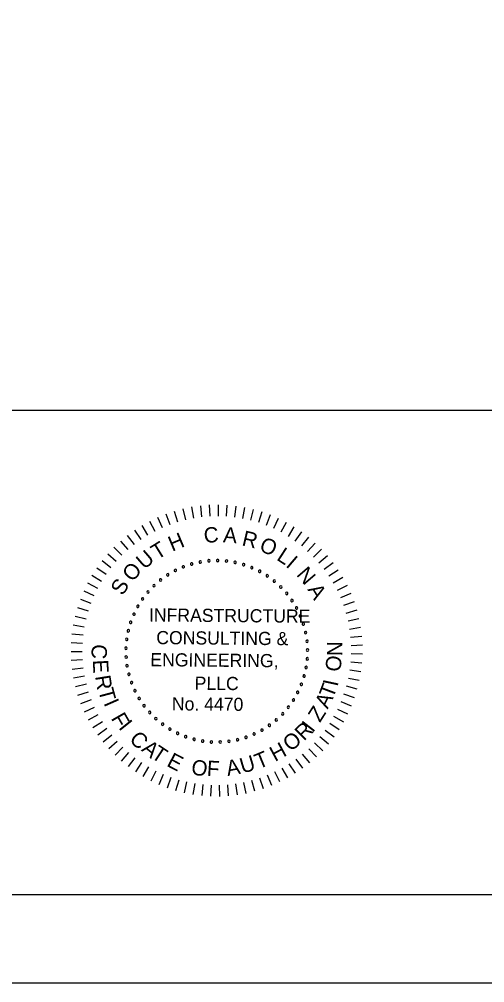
# Model space of a CAD drawing. Extents: x -133.1 to -97, y -1.8 to 20.5.
# Drawn here: x -107.93 to -105.29, y -1.69 to 3.78 of the extents above; entities that cross this region are included whole.
import ezdxf

# ---------------------------------------------------------------- set-up
doc = ezdxf.new("R2010")
doc.units = 0
for name, color, linetype in [('BR_BORDER LINES', 7, 'Continuous'), ('BR_TEXT', 7, 'Continuous'), ('Level 31', 7, 'Continuous')]:
    doc.layers.add(name, color=color, linetype=linetype)

msp = doc.modelspace()

# ---------------------------------------------------------------- linework, layer by layer
at = {"layer": 'BR_BORDER LINES'}
for p, q in [((-110.5071, 1.5591), (-105.1419, 1.5591)), ((-131.3076, -1.191), (-97.6416, -1.191))]:
    msp.add_line(p, q, dxfattribs=at)
at = {"layer": 'BR_TEXT'}
for p, q in [((-107.0494, 0.9866), (-107.0308, 0.9257)), ((-107.0007, 0.9998), (-106.9858, 0.9379)), ((-106.9512, 1.01), (-106.9401, 0.9473)), ((-106.9012, 1.0172), (-106.894, 0.9539)), ((-106.8509, 1.0213), (-106.8476, 0.9578)), ((-106.8005, 1.0224), (-106.801, 0.9587)), ((-106.75, 1.0204), (-106.7544, 0.9569)), ((-106.6998, 1.0153), (-106.7081, 0.9522)), ((-106.65, 1.0071), (-106.6621, 0.9446)), ((-106.6007, 0.996), (-106.6166, 0.9343)), ((-107.1439, 0.9513), (-107.1181, 0.8932)), ((-107.0972, 0.9704), (-107.0749, 0.9107)), ((-106.5523, 0.9818), (-106.5719, 0.9213)), ((-106.5048, 0.9648), (-106.528, 0.9055)), ((-106.4584, 0.9448), (-106.4852, 0.8871)), ((-107.276, 0.8776), (-107.24, 0.8251)), ((-107.2335, 0.9049), (-107.2008, 0.8503)), ((-107.1895, 0.9295), (-107.1601, 0.873)), ((-106.4133, 0.9221), (-106.4436, 0.8661)), ((-106.3697, 0.8967), (-106.4034, 0.8426)), ((-107.3168, 0.8478), (-107.2776, 0.7976)), ((-106.3277, 0.8686), (-106.3646, 0.8167)), ((-106.2875, 0.8381), (-106.3275, 0.7885)), ((-107.3925, 0.7811), (-107.3475, 0.736)), ((-107.3557, 0.8156), (-107.3135, 0.7679)), ((-106.2493, 0.8051), (-106.2922, 0.7581)), ((-106.2131, 0.7699), (-106.2588, 0.7256)), ((-107.4272, 0.7444), (-107.3795, 0.7022)), ((-106.1791, 0.7326), (-106.2275, 0.6911)), ((-107.4895, 0.665), (-107.437, 0.6289)), ((-107.4595, 0.7056), (-107.4094, 0.6664)), ((-106.1475, 0.6932), (-106.1983, 0.6548)), ((-107.5169, 0.6226), (-107.4623, 0.5897)), ((-106.1184, 0.652), (-106.1714, 0.6167)), ((-106.0918, 0.6091), (-106.1469, 0.5771)), ((-107.5416, 0.5786), (-107.4852, 0.5491)), ((-106.0679, 0.5646), (-106.1248, 0.5361)), ((-107.5637, 0.5332), (-107.5055, 0.5072)), ((-106.0467, 0.5188), (-106.1052, 0.4938)), ((-107.5992, 0.4387), (-107.5384, 0.42)), ((-107.5829, 0.4865), (-107.5233, 0.4641)), ((-106.0283, 0.4718), (-106.0883, 0.4504)), ((-107.6126, 0.3901), (-107.5507, 0.3751)), ((-106.0129, 0.4237), (-106.0741, 0.406)), ((-107.623, 0.3407), (-107.5604, 0.3295)), ((-106.0004, 0.3748), (-106.0625, 0.3608)), ((-107.6304, 0.2907), (-107.5672, 0.2834)), ((-105.9909, 0.3252), (-106.0538, 0.3151)), ((-105.9845, 0.2751), (-106.0479, 0.2689)), ((-107.6348, 0.2404), (-107.5712, 0.237)), ((-105.9811, 0.2247), (-106.0448, 0.2224)), ((-107.636, 0.19), (-107.5723, 0.1904)), ((-105.9809, 0.1743), (-106.0445, 0.1758)), ((-107.6342, 0.1395), (-107.5706, 0.1438)), ((-105.9836, 0.1239), (-106.0471, 0.1292)), ((-107.6293, 0.0893), (-107.5661, 0.0974)), ((-105.9895, 0.0737), (-106.0525, 0.0829)), ((-107.6213, 0.0394), (-107.5588, 0.0514)), ((-107.6103, -0.0099), (-107.5487, 0.0059)), ((-105.9984, 0.024), (-106.0607, 0.0371)), ((-107.5964, -0.0584), (-107.5358, -0.0388)), ((-106.0252, -0.0733), (-106.0855, -0.0527)), ((-106.0103, -0.025), (-106.0717, -0.0082)), ((-107.5795, -0.106), (-107.5202, -0.0828)), ((-106.043, -0.1205), (-106.1019, -0.0963)), ((-107.5597, -0.1524), (-107.5019, -0.1256)), ((-106.0636, -0.1666), (-106.1209, -0.1389)), ((-107.5371, -0.1976), (-107.4811, -0.1673)), ((-107.5119, -0.2413), (-107.4578, -0.2077)), ((-106.087, -0.2113), (-106.1426, -0.1802)), ((-107.484, -0.2834), (-107.4321, -0.2465)), ((-106.1418, -0.2961), (-106.1931, -0.2584)), ((-106.1131, -0.2545), (-106.1667, -0.22)), ((-107.4536, -0.3237), (-107.404, -0.2837)), ((-107.4208, -0.362), (-107.3737, -0.3191)), ((-106.173, -0.3358), (-106.2219, -0.2951)), ((-107.3857, -0.3983), (-107.3413, -0.3527)), ((-106.2423, -0.4092), (-106.2859, -0.3628)), ((-106.2065, -0.3735), (-106.2529, -0.3299)), ((-107.3485, -0.4324), (-107.307, -0.3841)), ((-107.3092, -0.4642), (-107.2708, -0.4135)), ((-106.32, -0.4736), (-106.3576, -0.4222)), ((-106.2801, -0.4426), (-106.3208, -0.3936)), ((-107.2681, -0.4935), (-107.2328, -0.4405)), ((-107.2253, -0.5203), (-107.1933, -0.4652)), ((-107.1809, -0.5444), (-107.1523, -0.4875)), ((-106.4049, -0.528), (-106.436, -0.4725)), ((-106.3616, -0.5021), (-106.3961, -0.4485)), ((-107.1352, -0.5657), (-107.1101, -0.5072)), ((-107.0882, -0.5842), (-107.0668, -0.5243)), ((-107.0402, -0.5998), (-107.0225, -0.5387)), ((-106.5915, -0.6041), (-106.6083, -0.5427)), ((-106.5432, -0.5894), (-106.5637, -0.5291)), ((-106.4959, -0.5718), (-106.52, -0.5128)), ((-106.4498, -0.5513), (-106.4774, -0.4939)), ((-106.9913, -0.6125), (-106.9773, -0.5504)), ((-106.9418, -0.6221), (-106.9316, -0.5593)), ((-106.8918, -0.6288), (-106.8854, -0.5654)), ((-106.8414, -0.6323), (-106.8389, -0.5687)), ((-106.7909, -0.6328), (-106.7923, -0.5691)), ((-106.7405, -0.6302), (-106.7458, -0.5667)), ((-106.6903, -0.6245), (-106.6995, -0.5615)), ((-106.6406, -0.6158), (-106.6536, -0.5535))]:
    msp.add_line(p, q, dxfattribs=at)
for centre, start, end in [((-106.8527, 0.7043), 5.0653, 185.0653), ((-106.8029, 0.7062), 359.5268, 179.5268), ((-107.0431, 0.6496), 27.2191, 207.2191), ((-106.9977, 0.6702), 21.6807, 201.6807), ((-106.9977, 0.6702), 201.6807, 21.6807), ((-106.9506, 0.6862), 16.1422, 196.1422), ((-106.9506, 0.6862), 196.1422, 16.1422), ((-106.9021, 0.6977), 10.6038, 190.6038), ((-106.9021, 0.6977), 190.6038, 10.6038), ((-106.8527, 0.7043), 185.0653, 5.0653), ((-106.8029, 0.7062), 179.5268, 359.5268), ((-106.7531, 0.7033), 173.9884, 353.9884), ((-106.7531, 0.7033), 353.9884, 173.9884), ((-106.7039, 0.6956), 168.4499, 348.4499), ((-106.7039, 0.6956), 348.4499, 168.4499), ((-106.6557, 0.6832), 162.9114, 342.9114), ((-106.6557, 0.6832), 342.9114, 162.9114), ((-106.6088, 0.6662), 157.373, 337.373), ((-106.6088, 0.6662), 337.373, 157.373), ((-107.127, 0.5959), 38.2961, 218.2961), ((-107.0864, 0.6248), 32.7576, 212.7576), ((-107.0864, 0.6248), 212.7576, 32.7576), ((-107.0431, 0.6496), 207.2191, 27.2191), ((-106.5639, 0.6447), 151.8345, 331.8345), ((-106.5639, 0.6447), 331.8345, 151.8345), ((-106.5212, 0.619), 146.2961, 326.2961), ((-106.5212, 0.619), 326.2961, 146.2961), ((-107.1646, 0.5633), 43.8345, 223.8345), ((-107.1646, 0.5633), 223.8345, 43.8345), ((-107.127, 0.5959), 218.2961, 38.2961), ((-106.4811, 0.5893), 140.7576, 320.7576), ((-106.4811, 0.5893), 320.7576, 140.7576), ((-106.4442, 0.5559), 135.2191, 315.2191), ((-106.4442, 0.5559), 315.2191, 135.2191), ((-107.2296, 0.4879), 54.9114, 234.9114), ((-107.2296, 0.4879), 234.9114, 54.9114), ((-107.1989, 0.5271), 49.373, 229.373), ((-107.1989, 0.5271), 229.373, 49.373), ((-106.4106, 0.5191), 129.6807, 309.6807), ((-106.4106, 0.5191), 309.6807, 129.6807), ((-107.2563, 0.4458), 60.4499, 240.4499), ((-107.2563, 0.4458), 240.4499, 60.4499), ((-106.3808, 0.4792), 124.1422, 304.1422), ((-106.3808, 0.4792), 304.1422, 124.1422), ((-106.3549, 0.4366), 118.6038, 298.6038), ((-106.3549, 0.4366), 298.6038, 118.6038), ((-107.2788, 0.4014), 65.9884, 245.9884), ((-107.2788, 0.4014), 245.9884, 65.9884), ((-106.3333, 0.3917), 113.0653, 293.0653), ((-106.3333, 0.3917), 293.0653, 113.0653), ((-107.297, 0.3549), 71.5268, 251.5268), ((-107.297, 0.3549), 251.5268, 71.5268), ((-106.3161, 0.3449), 107.5268, 287.5268), ((-106.3161, 0.3449), 287.5268, 107.5268), ((-107.3106, 0.307), 77.0653, 257.0653), ((-107.3106, 0.307), 257.0653, 77.0653), ((-106.3035, 0.2967), 101.9884, 281.9884), ((-106.3035, 0.2967), 281.9884, 101.9884), ((-107.3195, 0.258), 82.6038, 262.6038), ((-107.3195, 0.258), 262.6038, 82.6038), ((-106.2956, 0.2475), 96.4499, 276.4499), ((-106.2956, 0.2475), 276.4499, 96.4499), ((-107.3236, 0.2083), 88.1422, 268.1422), ((-107.3229, 0.1585), 93.6807, 273.6807), ((-107.3236, 0.2083), 268.1422, 88.1422), ((-107.3229, 0.1585), 273.6807, 93.6807), ((-106.2925, 0.1977), 90.9114, 270.9114), ((-106.2925, 0.1977), 270.9114, 90.9114), ((-107.3174, 0.109), 99.2191, 279.2191), ((-107.3174, 0.109), 279.2191, 99.2191), ((-106.2942, 0.1479), 85.373, 265.373), ((-106.2942, 0.1479), 265.373, 85.373), ((-107.3071, 0.0602), 104.7576, 284.7576), ((-107.3071, 0.0602), 284.7576, 104.7576), ((-106.312, 0.05), 74.2961, 254.2961), ((-106.312, 0.05), 254.2961, 74.2961), ((-106.3007, 0.0985), 79.8345, 259.8345), ((-106.3007, 0.0985), 259.8345, 79.8345), ((-107.2922, 0.0126), 110.2961, 290.2961), ((-107.2922, 0.0126), 290.2961, 110.2961), ((-106.3279, 0.0028), 68.7576, 248.7576), ((-106.3279, 0.0028), 248.7576, 68.7576), ((-107.2728, -0.0332), 115.8345, 295.8345), ((-107.2728, -0.0332), 295.8345, 115.8345), ((-106.3483, -0.0427), 63.2191, 243.2191), ((-106.3483, -0.0427), 243.2191, 63.2191), ((-107.249, -0.077), 121.373, 301.373), ((-107.249, -0.077), 301.373, 121.373), ((-106.3729, -0.086), 57.6807, 237.6807), ((-106.3729, -0.086), 237.6807, 57.6807), ((-107.2211, -0.1183), 126.9114, 306.9114), ((-107.2211, -0.1183), 306.9114, 126.9114), ((-107.1894, -0.1567), 132.4499, 312.4499), ((-107.1894, -0.1567), 312.4499, 132.4499), ((-106.4342, -0.1645), 46.6038, 226.6038), ((-106.4342, -0.1645), 226.6038, 46.6038), ((-106.4016, -0.1267), 52.1422, 232.1422), ((-106.4016, -0.1267), 232.1422, 52.1422), ((-107.1541, -0.1919), 137.9884, 317.9884), ((-107.1541, -0.1919), 317.9884, 137.9884), ((-107.1156, -0.2235), 323.5268, 143.5268), ((-106.4702, -0.1989), 41.0653, 221.0653), ((-106.4702, -0.1989), 221.0653, 41.0653), ((-107.1156, -0.2235), 143.5268, 323.5268), ((-107.0742, -0.2512), 149.0653, 329.0653), ((-107.0742, -0.2512), 329.0653, 149.0653), ((-107.0303, -0.2749), 154.6038, 334.6038), ((-107.0303, -0.2749), 334.6038, 154.6038), ((-106.5957, -0.2793), 24.4499, 204.4499), ((-106.5513, -0.2566), 29.9884, 209.9884), ((-106.5513, -0.2566), 209.9884, 29.9884), ((-106.5093, -0.2297), 35.5268, 215.5268), ((-106.5093, -0.2297), 215.5268, 35.5268), ((-106.9843, -0.2941), 160.1422, 340.1422), ((-106.9843, -0.2941), 340.1422, 160.1422), ((-106.9367, -0.3089), 165.6807, 345.6807), ((-106.9367, -0.3089), 345.6807, 165.6807), ((-106.8879, -0.3189), 171.2191, 351.2191), ((-106.8879, -0.3189), 351.2191, 171.2191), ((-106.8384, -0.3242), 356.7576, 176.7576), ((-106.8384, -0.3242), 176.7576, 356.7576), ((-106.7885, -0.3248), 2.2961, 182.2961), ((-106.7885, -0.3248), 182.2961, 2.2961), ((-106.7389, -0.3205), 7.8345, 187.8345), ((-106.7389, -0.3205), 187.8345, 7.8345), ((-106.6899, -0.3114), 13.373, 193.373), ((-106.6899, -0.3114), 193.373, 13.373), ((-106.642, -0.2976), 18.9114, 198.9114), ((-106.642, -0.2976), 198.9114, 18.9114), ((-106.5957, -0.2793), 204.4499, 24.4499)]:
    msp.add_arc(centre, 0.00701, start, end, dxfattribs=at)
at = {"layer": 'Level 31'}
msp.add_lwpolyline([(-133.1409, -1.691), (-97.141, -1.691), (-97.141, 20.309), (-133.1409, 20.309)], close=True, dxfattribs=at)

# ---------------------------------------------------------------- texts
at = {"layer": 'BR_TEXT'}
for s, height, rotation, p in [('C', 0.0872, 4.7281, (-106.8784, 0.8048)), ('A', 0.0872, 355.6981, (-106.7739, 0.8098)), ('R', 0.0872, 346.6681, (-106.6696, 0.7928)), ('H', 0.0872, 22.7882, (-107.0612, 0.7554)), ('O', 0.0872, 337.638, (-106.5719, 0.763)), ('U', 0.0872, 40.8482, (-107.2194, 0.6516)), ('T', 0.0872, 31.8182, (-107.1461, 0.7078)), ('L', 0.0872, 327.108, (-106.4731, 0.7125)), ('I', 0.0872, 319.578, (-106.4205, 0.6747)), ('O', 0.0872, 49.8782, (-107.2864, 0.5806)), ('N', 0.0872, 310.548, (-106.3597, 0.6239)), ('S', 0.0872, 58.9083, (-107.3418, 0.5024)), ('A', 0.0872, 301.5179, (-106.2946, 0.5415)), ('INFRASTRUCTURE', 0.074771, 359.5268, (-107.1932, 0.3599)), ('CONSULTING &', 0.074771, 359.5268, (-107.1519, 0.2313)), ('C', 0.0872, 267.025, (-107.5168, 0.2325)), ('N', 0.0872, 89.2085, (-106.0953, 0.1628)), ('ENGINEERING,', 0.074771, 359.5268, (-107.1855, 0.1059)), ('E', 0.0872, 273.025, (-107.5124, 0.1409)), ('O', 0.0872, 83.2085, (-106.1064, 0.0713)), ('R', 0.0872, 279.025, (-107.4996, 0.0487)), ('PLLC', 0.07477, 359.5268, (-106.9338, -0.0277)), ('T', 0.0872, 69.3954, (-106.1476, -0.0805)), ('I', 0.0872, 77.9093, (-106.1219, -0.013)), ('T', 0.0872, 285.025, (-107.4822, -0.0301)), ('I', 0.0872, 293.7713, (-107.4525, -0.1032)), ('No. 4470', 0.07477, 359.5268, (-107.0633, -0.1446)), ('A', 0.0872, 63.3954, (-106.1784, -0.1408)), ('F', 0.0872, 299.7713, (-107.4113, -0.1893)), ('Z', 0.0872, 57.3954, (-106.2222, -0.2172)), ('I', 0.0872, 308.5268, (-107.3692, -0.2431)), ('R', 0.0872, 44.5268, (-106.3127, -0.3221)), ('I', 0.0872, 52.3339, (-106.2633, -0.2748)), ('C', 0.0872, 314.5268, (-107.3099, -0.3133)), ('A', 0.0872, 320.5268, (-107.2407, -0.3718)), ('H', 0.0872, 28.5268, (-106.4774, -0.4381)), ('O', 0.0872, 38.5268, (-106.3893, -0.3821)), ('T', 0.0872, 326.5268, (-107.1863, -0.4103)), ('T', 0.0872, 22.5268, (-106.5706, -0.4799)), ('E', 0.0872, 332.5268, (-107.0977, -0.4581)), ('O', 0.0872, 350.5268, (-106.9576, -0.507)), ('F', 0.0872, 356.5268, (-106.8661, -0.5161)), ('A', 0.0872, 10.5268, (-106.7462, -0.5177)), ('U', 0.0872, 16.5268, (-106.6623, -0.5042))]:
    msp.add_text(s, height=height, rotation=rotation, dxfattribs=at).set_placement(p)

doc.saveas('drawing.dxf')
